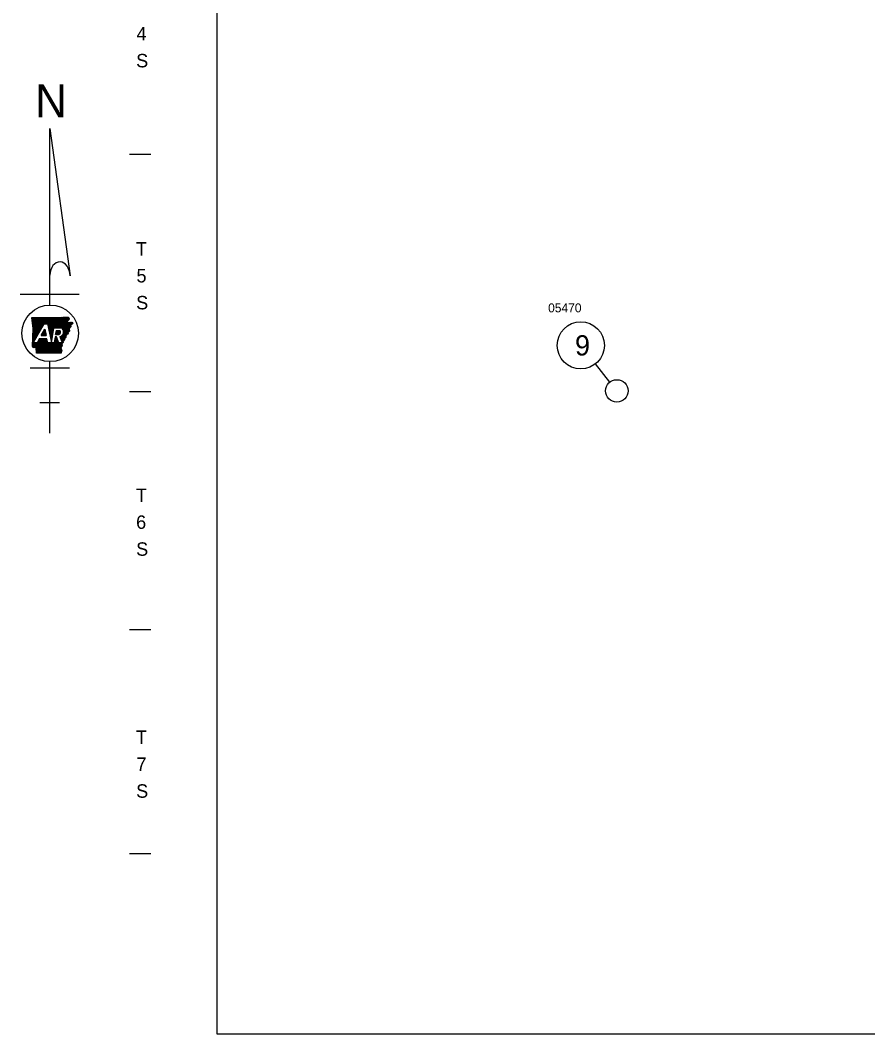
# Model space of a CAD drawing. Extents: x -33639 to 34530, y -17264 to 5867.
# Drawn here: x 4455 to 8232, y -3279 to 1239 of the extents above; entities that cross this region are included whole.
import ezdxf

# ---------------------------------------------------------------- set-up
doc = ezdxf.new("R2010")
doc.units = 0
for name, color, linetype in [('2', 7, 'Continuous'), ('Default', 7, 'Continuous'), ('R_Annotation', 7, 'Continuous'), ('R_No Plot', 7, 'Continuous')]:
    doc.layers.add(name, color=color, linetype=linetype)

msp = doc.modelspace()

# ---------------------------------------------------------------- linework, layer by layer
at = {"layer": 'Default'}
for p, q in [((5037.5, 639.8), (4942.5, 639.8)), ((5037.5, -416.9), (4942.5, -416.9)), ((5037.5, -1478.9), (4942.5, -1478.9)), ((5037.5, -2478.1), (4942.5, -2478.1))]:
    msp.add_line(p, q, dxfattribs=at)
at = {"layer": 'R_Annotation'}
for p, q in [((4586.6, 757.1), (4677.5, 100.1)), ((4586.6, -30.8), (4586.6, 757.1)), ((4455, 17.9), (4718.1, 17.9)), ((4506.7, -87.2), (4507.8, -86.2)), ((4507.1, -90.3), (4511.3, -86.2)), ((4507.5, -93.4), (4514.8, -86.2)), ((4507.9, -96.5), (4518.3, -86.2)), ((4508.3, -99.6), (4521.7, -86.2)), ((4508.7, -102.7), (4525.2, -86.2)), ((4509, -105.8), (4528.7, -86.2)), ((4509.4, -108.9), (4532.2, -86.2)), ((4509.8, -112), (4535.7, -86.2)), ((4510.2, -115.1), (4539.1, -86.2)), ((4510.6, -118.2), (4542.6, -86.2)), ((4511, -121.3), (4546.1, -86.2)), ((4511.4, -124.4), (4549.6, -86.2)), ((4511.7, -127.5), (4553.1, -86.2)), ((4511.9, -162.2), (4588, -86.1)), ((4512, -158.6), (4584.5, -86.1)), ((4512.1, -155), (4581, -86.1)), ((4512.1, -130.6), (4556.5, -86.2)), ((4512.2, -151.4), (4577.5, -86.1)), ((4512.3, -147.8), (4574, -86.2)), ((4512.5, -144.2), (4570.5, -86.2)), ((4512.5, -133.7), (4560, -86.2)), ((4512.6, -140.6), (4567, -86.2)), ((4512.7, -137), (4563.5, -86.2)), ((4563.6, -114), (4591.4, -86.1)), ((4567.1, -114), (4594.9, -86.1)), ((4570.5, -114), (4598.5, -86.1)), ((4574, -114), (4602, -86)), ((4576.2, -115.3), (4605.5, -86)), ((4576.8, -118.2), (4609.1, -85.9)), ((4577.4, -121), (4612.6, -85.9)), ((4578, -123.9), (4616.1, -85.8)), ((4578.6, -126.8), (4619.7, -85.7)), ((4579.3, -129.6), (4623.2, -85.7)), ((4579.9, -132.5), (4626.8, -85.6)), ((4580.5, -135.4), (4630.3, -85.6)), ((4581.1, -138.2), (4633.8, -85.5)), ((4581.7, -141.1), (4637.4, -85.5)), ((4582.3, -144), (4640.9, -85.4)), ((4582.9, -146.9), (4644.4, -85.4)), ((4583.6, -149.7), (4648, -85.3)), ((4584.2, -152.6), (4651.6, -85.2)), ((4608.4, -131.9), (4655.1, -85.1)), ((4611.9, -131.9), (4658.7, -85)), ((4615.3, -131.9), (4662.3, -85)), ((4618.8, -131.9), (4665.8, -84.9)), ((4622.3, -131.9), (4669.4, -84.8)), ((4625.8, -131.9), (4670.2, -87.5)), ((4629.3, -131.9), (4671.8, -89.3)), ((4511.5, -173), (4549.6, -134.9)), ((4511.6, -169.4), (4554.2, -126.9)), ((4511.7, -165.8), (4558.7, -118.8)), ((4512.9, -199.8), (4561.5, -114)), ((4561.5, -114), (4575.9, -114)), ((4605.2, -131.9), (4639, -131.9)), ((4632.7, -131.9), (4672.3, -92.3)), ((4636.2, -131.9), (4664.3, -103.8)), ((4639.4, -132.2), (4663.7, -107.9)), ((4641.3, -133.8), (4667.3, -107.8)), ((4643, -135.6), (4671, -107.6)), ((4644.4, -162), (4671, -135.4)), ((4644.5, -137.5), (4674.7, -107.4)), ((4645.8, -139.7), (4678.3, -107.2)), ((4646.9, -142.2), (4682, -107)), ((4647.4, -155.5), (4679, -123.9)), ((4647.7, -144.8), (4685.3, -107.2)), ((4648.1, -147.8), (4686.9, -109)), ((4648.2, -151.3), (4678.6, -120.8)), ((4675.1, -131.3), (4679.4, -127)), ((4685.4, -114.1), (4688.6, -110.9)), ((4510.9, -191), (4526.9, -175)), ((4511, -187.4), (4531.5, -167)), ((4511.1, -183.8), (4536, -159)), ((4511.3, -180.2), (4540.5, -150.9)), ((4511.4, -176.6), (4545.1, -142.9)), ((4548.6, -166.1), (4564.5, -138)), ((4548.6, -166.1), (4570.5, -166.1)), ((4548.8, -166.1), (4566.7, -148.2)), ((4552.3, -166.1), (4567.3, -151.1)), ((4553, -158.5), (4566.1, -145.3)), ((4555.8, -166.1), (4567.9, -153.9)), ((4557.5, -150.4), (4565.5, -142.5)), ((4559.2, -166.1), (4568.5, -156.8)), ((4562, -142.4), (4564.9, -139.6)), ((4562.7, -166.1), (4569.2, -159.7)), ((4566.2, -166.1), (4569.8, -162.6)), ((4569.7, -166.1), (4570.4, -165.4)), ((4584.8, -155.5), (4604.6, -135.7)), ((4585.4, -158.3), (4603.8, -139.9)), ((4586, -161.2), (4603.1, -144.1)), ((4586.6, -164.1), (4602.3, -148.4)), ((4587.2, -166.9), (4601.6, -152.6)), ((4587.9, -169.8), (4600.9, -156.8)), ((4588.5, -172.7), (4600.1, -161)), ((4589.1, -175.5), (4599.4, -165.2)), ((4589.7, -178.4), (4598.7, -169.4)), ((4590.3, -181.3), (4597.9, -173.7)), ((4590.9, -184.2), (4597.2, -177.9)), ((4607.3, -192.1), (4619.4, -180.1)), ((4608.1, -187.9), (4618.5, -177.5)), ((4608.8, -183.7), (4617.5, -175)), ((4609.6, -179.5), (4616.5, -172.5)), ((4610.3, -175.2), (4613, -172.5)), ((4616.6, -172.5), (4610.8, -172.5)), ((4612.5, -162.3), (4627, -162.3)), ((4612.6, -162.3), (4630.9, -144)), ((4613.3, -158.1), (4627.4, -144)), ((4614, -153.9), (4623.9, -144)), ((4614.7, -149.7), (4620.4, -144)), ((4615.5, -145.5), (4617, -144)), ((4615.7, -144), (4631.6, -144)), ((4616, -162.3), (4632.8, -145.5)), ((4626.7, -199.8), (4616.6, -172.5)), ((4619.5, -162.3), (4634, -147.8)), ((4623, -162.3), (4634.6, -150.7)), ((4626.5, -162.3), (4634.3, -154.5)), ((4630.9, -171), (4641.5, -199.8)), ((4631.2, -171.8), (4632.2, -170.7)), ((4632.1, -174.3), (4638.7, -167.7)), ((4633, -176.9), (4671.7, -138.3)), ((4634, -179.4), (4672.3, -141.1)), ((4634.9, -182), (4673, -143.9)), ((4635.9, -184.5), (4673.6, -146.7)), ((4636.8, -187), (4657.7, -166.1)), ((4637.7, -189.6), (4657.3, -170)), ((4638.7, -192.1), (4656.9, -173.9)), ((4661.7, -162.1), (4666.6, -157.2)), ((4510.1, -216.2), (4526.5, -199.8)), ((4510.2, -212.7), (4523.1, -199.8)), ((4510.3, -209.1), (4519.6, -199.8)), ((4510.4, -205.5), (4516.1, -199.8)), ((4510.5, -201.8), (4513.3, -199.1)), ((4510.7, -198.2), (4517.8, -191.1)), ((4510.8, -194.6), (4522.4, -183.1)), ((4511.4, -218.4), (4548, -181.8)), ((4529.6, -199.8), (4512.9, -199.8)), ((4513.5, -219.8), (4551.5, -181.8)), ((4516, -220.8), (4555, -181.8)), ((4520.1, -220.1), (4558.5, -181.8)), ((4523.7, -220.1), (4562, -181.8)), ((4526.4, -220.8), (4565.4, -181.8)), ((4526.5, -227.7), (4572.4, -181.8)), ((4526.5, -224.2), (4568.9, -181.8)), ((4526.5, -231.1), (4574.2, -183.4)), ((4526.5, -234.6), (4574.8, -186.3)), ((4526.5, -238.1), (4575.5, -189.2)), ((4526.5, -241.6), (4576.1, -192)), ((4526.6, -245), (4576.7, -194.9)), ((4539.8, -181.8), (4529.6, -199.8)), ((4530.1, -245), (4577.3, -197.8)), ((4533.5, -192.8), (4544.5, -181.8)), ((4533.6, -245), (4578.8, -199.8)), ((4537, -245), (4582.3, -199.8)), ((4538.1, -184.8), (4541.1, -181.8)), ((4573.9, -181.8), (4539.8, -181.8)), ((4540.5, -245), (4585.7, -199.8)), ((4544, -245), (4589.2, -199.8)), ((4547.5, -245), (4592.7, -199.8)), ((4550.9, -245), (4596.2, -199.8)), ((4554.4, -245), (4599.7, -199.8)), ((4557.9, -245), (4603.2, -199.8)), ((4561.4, -245), (4621.3, -185.1)), ((4564.9, -245.1), (4622.2, -187.7)), ((4568.3, -245.1), (4623.2, -190.2)), ((4571.8, -245.1), (4624.1, -192.8)), ((4575.3, -245.1), (4625, -195.3)), ((4606, -199.8), (4577.7, -199.8)), ((4578.8, -245.1), (4626, -197.9)), ((4582.2, -245.1), (4627.5, -199.8)), ((4585.7, -245.1), (4631, -199.8)), ((4589.2, -245.1), (4634.5, -199.8)), ((4591.5, -187), (4596.5, -182.1)), ((4592.2, -189.9), (4595.7, -186.3)), ((4592.7, -245.1), (4638, -199.8)), ((4592.8, -192.8), (4595, -190.5)), ((4593.4, -195.6), (4594.3, -194.8)), ((4596.2, -245.1), (4639.2, -202.1)), ((4599.6, -245.1), (4639.3, -205.4)), ((4603.1, -245.1), (4639.5, -208.8)), ((4606.6, -196.3), (4620.3, -182.6)), ((4606.6, -245.1), (4639.6, -212.1)), ((4610.1, -245.1), (4633.9, -221.3)), ((4613.5, -245.1), (4635, -223.7)), ((4641.5, -199.8), (4626.7, -199.8)), ((4639.6, -194.7), (4650.3, -184)), ((4640.6, -197.2), (4648.8, -189)), ((4617, -245.1), (4636, -226.1)), ((4620.5, -245.1), (4637.1, -228.5)), ((4624, -245.1), (4638.2, -230.9)), ((4627.4, -245.2), (4639.1, -233.5)), ((4630.9, -245.2), (4637.5, -238.6)), ((4634.4, -245.2), (4635.9, -243.6)), ((4498.8, -310), (4674.3, -310)), ((4586.6, -602.6), (4586.6, -282.9)), ((7082.7, -374.3), (7018.3, -292.8)), ((4542.7, -465.8), (4630.4, -465.8))]:
    msp.add_line(p, q, dxfattribs=at)
for points in [[(4506.6, -86.2), (4554.6, -86.2), (4596.8, -86.1), (4646.6, -85.3), (4669.6, -84.8)], [(4506.6, -86.2), (4554.6, -86.2), (4596.8, -86.1), (4646.5, -85.3), (4669.6, -84.8)], [(4511.9, -160.9), (4512.7, -135.5), (4506.6, -86.2)], [(4510.1, -216.2), (4512.7, -135.5), (4506.6, -86.2)], [(4575.9, -114), (4593.8, -197.5), (4605.2, -131.9)], [(4684.7, -106.9), (4688.9, -111.2), (4678.5, -119.7), (4679.6, -128.3), (4670.7, -134.2), (4673.8, -147.4), (4666.9, -153.7), (4666.3, -160.5), (4658, -163.5), (4656.7, -176.3), (4650.7, -182.7), (4647.8, -192.4), (4639.1, -200.4), (4639.7, -214.4), (4633.8, -221.1), (4639.2, -233.2), (4635.5, -245.2)], [(4662.5, -108), (4685, -106.8)], [(4662.5, -108), (4685, -106.8)], [(4510.1, -216.2), (4511.9, -160.9)], [(4564.5, -138), (4570.5, -166.1)], [(4610.8, -172.5), (4606, -199.8)], [(4612.5, -162.3), (4615.7, -144)], [(4635.5, -245.2), (4526.6, -245), (4526.5, -220.9)], [(4635.5, -245.2), (4526.6, -245), (4526.5, -220.9)], [(4577.7, -199.8), (4573.9, -181.8)]]:
    msp.add_lwpolyline(points, dxfattribs=at)
for centre, radius in [((6953.2, -210.4), 105), ((7113.7, -413.5), 50)]:
    msp.add_circle(centre, radius, dxfattribs=at)
for centre, major_axis, ratio, start_param, end_param in [((4632, 98.6), (-1.9, 63.2), 0.719778, 4.712385, 7.768526), ((4626.4, -149.7), (-21.8, 0), 0.999987, 1.777838, 4.099264), ((4623.5, -151.7), (-11.1, 0), 0.999987, 1.887169, 3.90762)]:
    msp.add_ellipse(centre, major_axis=major_axis, ratio=ratio, start_param=start_param, end_param=end_param, dxfattribs=at)
msp.add_ellipse((4588.6, -156.8), major_axis=(126, 0), ratio=0.999976, dxfattribs=at)
for points in [[(4669.6, -84.8), (4669.8, -86.1), (4670.2, -86.8), (4670.2, -88), (4670.7, -88.6), (4671.6, -89.1), (4672.3, -90), (4672.5, -91), (4672.3, -92), (4672.2, -93.2), (4672.1, -94.2), (4671.9, -95.1), (4671.2, -95.9), (4670.6, -96.4), (4669.9, -97), (4669.5, -97.7), (4668.7, -98.4), (4667.9, -99.1), (4667.3, -99.8), (4666.7, -100.6), (4666.4, -101.5), (4665.7, -102.2), (4665.2, -102.8), (4664.5, -103.6), (4664.1, -104.4), (4663.4, -105.3), (4663.3, -106.2), (4662.8, -106.9), (4662.8, -107)], [(4669.6, -84.8), (4669.8, -86.1), (4670.2, -86.8), (4670.2, -88), (4670.7, -88.6), (4671.6, -89.1), (4672.4, -90), (4672.5, -91), (4672.3, -92), (4672.3, -93.2), (4672.1, -94.2), (4672, -95.1), (4671.2, -95.8), (4670.6, -96.4), (4669.9, -97), (4669.5, -97.7), (4668.7, -98.4), (4667.9, -99.1), (4667.3, -99.8), (4666.7, -100.6), (4666.4, -101.5), (4665.7, -102.2), (4665.2, -102.8), (4664.5, -103.6), (4664.1, -104.4), (4663.4, -105.3), (4663.3, -106.2), (4662.8, -106.9), (4662.8, -107)], [(4673.4, -135.5), (4673.5, -136.3), (4673, -137.2), (4672.8, -138.2), (4672.9, -139.1), (4671.9, -139.6), (4671.1, -140.2), (4671.6, -140.9), (4672.5, -141.5), (4673.4, -142), (4673.9, -142.6), (4674.1, -143.8), (4674.2, -144.6), (4674.6, -145.6), (4674.7, -146.4), (4674.1, -147.2), (4673.5, -147.4), (4672.8, -147.2), (4672.1, -147.2), (4671.5, -147.7), (4671, -148.6), (4670.6, -149.4), (4670.2, -150.1), (4669.9, -150.9), (4669.3, -151.8), (4668.5, -151.9), (4667.5, -152.2), (4666.9, -152.8), (4667, -153.9), (4667.6, -154.7), (4668, -155.6), (4668.3, -156.4), (4668.1, -157.4), (4667.7, -158.2), (4667.2, -158.6), (4666.9, -159.6), (4666.5, -160.3), (4666.2, -160.5), (4665.5, -160.5), (4664.7, -160.3), (4664.1, -160.4), (4663.4, -160.7), (4662.8, -160.5), (4662.1, -159.8), (4661.6, -159.2), (4661, -159), (4660.4, -159.3), (4660.3, -160.3), (4660.6, -161.3), (4660.8, -162.7), (4660.6, -163.5), (4660.5, -164.9)], [(4684.7, -106.9), (4685, -106.8), (4686, -107.9), (4686.5, -108.8), (4687.1, -109.3), (4687.9, -109.6), (4688.4, -110.3), (4688.8, -111), (4688.6, -111.7), (4687.8, -111.7), (4686.9, -111.9), (4686, -111.8), (4685.3, -112.4), (4685.9, -113.2), (4686.8, -114), (4687, -114.8), (4686.5, -115.5), (4685.6, -116), (4684.7, -116.3), (4683.8, -117), (4683.4, -117.7), (4682.5, -118), (4681.6, -118.3), (4680.8, -118.4), (4679.8, -118.6), (4678.9, -119), (4678.5, -119.8), (4678.6, -120.9), (4678.6, -122), (4679.6, -122.4), (4680.4, -122.5), (4681.3, -122.9), (4681.2, -123.5), (4680.5, -124.4), (4679.8, -125), (4679.1, -125.4), (4678.4, -126), (4678.6, -126.6), (4679.2, -127), (4679.7, -127.7), (4679.6, -128.3), (4678.9, -128.8), (4678.1, -128.6), (4677.6, -127.8), (4676.9, -127.6), (4676.3, -127.3), (4675.7, -127.7), (4675.7, -128.6), (4675.5, -129.5), (4675.7, -130.2), (4675.9, -131.1), (4675.9, -131.9), (4675.7, -132.9), (4675.2, -133.9), (4674.6, -134.2), (4674.3, -133.1), (4674.2, -132.2), (4673.8, -131.6), (4673.4, -131.6), (4672.7, -132.1), (4672.1, -132.8), (4671.2, -133.5), (4670.7, -134.2), (4671, -135.2), (4671.6, -135.4), (4672.1, -135.2), (4672.4, -134.6), (4672.9, -134.5), (4673.4, -135.5)], [(4660.5, -164.9), (4659.4, -165.7), (4659, -166.5), (4656.3, -166.3), (4656.4, -167.2), (4655.5, -167.7), (4654.6, -168.3), (4655.1, -169), (4656, -169.7), (4656.9, -170.2), (4657.5, -170.7), (4657.6, -171.9), (4657.8, -172.7), (4658.1, -173.8), (4658.2, -174.5), (4657.6, -175.4), (4657, -175.6), (4656.4, -175.3), (4655.6, -175.3), (4655, -175.9), (4654.5, -176.7), (4654.1, -177.6), (4653.7, -178.3), (4653.4, -179), (4652.8, -179.9), (4652, -180.1), (4651, -180.3), (4650.4, -180.9), (4650.5, -182.1), (4651.1, -182.8), (4651.5, -183.7), (4651.8, -184.5), (4651.7, -185.5), (4651.2, -186.3), (4650.7, -186.7), (4650.4, -187.7), (4650.1, -188.4), (4649.7, -188.6), (4649, -188.6), (4648.2, -188.4), (4647.6, -188.5), (4647, -188.8), (4646.3, -188.6), (4645.7, -187.9), (4645.1, -187.3), (4644.5, -187.1), (4643.9, -187.5), (4643.8, -188.5), (4644.1, -189.5), (4644.4, -190.8), (4644.1, -191.6), (4644, -193)], [(4526.5, -220.9), (4526.6, -221), (4526.1, -220.6), (4525.3, -220.2), (4524.4, -220.2), (4523.3, -220), (4522.4, -219.9), (4521.5, -219.3), (4520.4, -220), (4519.3, -220.4), (4518.7, -219.9), (4517.8, -220.3), (4517.2, -220.1), (4516.2, -220.8), (4515.2, -220.5), (4514.5, -220.7), (4513.6, -220.7), (4513.4, -219.7), (4512.5, -219.6), (4511.8, -219.1), (4511.3, -218.1), (4510.9, -217.3), (4510.1, -216.2)], [(4526.5, -220.9), (4526.6, -221), (4526.1, -220.6), (4525.3, -220.2), (4524.4, -220.2), (4523.3, -220), (4522.4, -219.9), (4521.4, -219.3), (4520.4, -220), (4519.3, -220.4), (4518.7, -219.9), (4517.8, -220.3), (4517.2, -220.1), (4516.2, -220.8), (4515.2, -220.5), (4514.5, -220.7), (4513.6, -220.7), (4513.4, -219.7), (4512.5, -219.6), (4511.8, -219.1), (4511.3, -218.1), (4510.9, -217.3), (4510.1, -216.2)], [(4640, -204.2), (4639.7, -204.9), (4639.4, -206.1), (4639.5, -207.1), (4639.9, -208), (4640.6, -208.4), (4641.4, -209.1), (4641.4, -210.2), (4640.9, -210.5), (4639.8, -210.3), (4639, -209.9), (4638.4, -210.1), (4637.5, -210.6), (4636.8, -210.7), (4636.8, -212.1), (4637.7, -213.1), (4638.5, -213.1), (4639.5, -213.2), (4639.8, -214.3), (4639.2, -215.2), (4638.4, -215.6), (4637.2, -215.1), (4636.4, -214.5), (4635.6, -214), (4634.6, -213.7), (4634, -213.8), (4633.8, -215.1), (4634.2, -216.2), (4635, -217), (4635.7, -218), (4635.6, -218.8), (4635.1, -219), (4634.1, -219.2), (4633.6, -219.5), (4633.4, -219.7), (4633.7, -220.7), (4634, -221.8), (4634, -222.7), (4633.6, -223.4), (4633.1, -224.6), (4633.2, -225.4), (4633.6, -225.7), (4634, -225.6), (4634.6, -225.2), (4635, -224.7), (4635.3, -224.1), (4635.9, -223.6), (4636.7, -224.1), (4636.9, -225), (4636.4, -225.8), (4635.8, -226.2), (4635.1, -226.5), (4634.5, -227.1), (4634.6, -227.9), (4635.1, -228.3), (4636.2, -228.1), (4636.9, -227.7), (4637.3, -227.4), (4637.8, -226.8), (4638.1, -226.3), (4638.5, -225.8), (4639.2, -225.6), (4639.5, -226.1), (4639.4, -227.1), (4639, -228.1), (4638.4, -228.8), (4637.8, -229.4), (4637, -230.6), (4637.2, -231.8), (4637.5, -232.7), (4637.9, -233.4), (4638.6, -233.3), (4639.4, -233.2), (4639.8, -233.5), (4639.8, -234.4), (4639.2, -235.2), (4638.6, -236), (4638.4, -237), (4638.5, -237.8), (4638.5, -238.4), (4638.2, -239.2), (4637.8, -239.6), (4636.7, -239.6), (4635.6, -239.5), (4634.9, -239.8), (4635.1, -240.8), (4635.7, -241.6), (4636.2, -242), (4636.9, -242.8), (4637.2, -243.5), (4637.1, -244.1), (4636.7, -244.6), (4635.5, -245.2)], [(4640, -204.2), (4639.7, -204.9), (4639.4, -206.1), (4639.5, -207.1), (4639.9, -208), (4640.6, -208.4), (4641.4, -209.1), (4641.4, -210.2), (4640.9, -210.5), (4639.8, -210.3), (4639, -209.9), (4638.4, -210.1), (4637.5, -210.6), (4636.8, -210.7), (4636.8, -212.1), (4637.7, -213.1), (4638.5, -213.1), (4639.5, -213.2), (4639.8, -214.3), (4639.2, -215.2), (4638.4, -215.6), (4637.2, -215.1), (4636.4, -214.5), (4635.6, -214), (4634.6, -213.7), (4634, -213.8), (4633.8, -215.1), (4634.2, -216.2), (4635, -217), (4635.7, -218), (4635.6, -218.8), (4635.1, -219), (4634.1, -219.2), (4633.6, -219.5), (4633.4, -219.7), (4633.7, -220.7), (4634, -221.8), (4634, -222.7), (4633.6, -223.4), (4633.1, -224.6), (4633.2, -225.4), (4633.6, -225.7), (4634, -225.6), (4634.6, -225.2), (4635, -224.7), (4635.3, -224.1), (4635.9, -223.6), (4636.7, -224.1), (4636.9, -225), (4636.4, -225.8), (4635.8, -226.2), (4635.1, -226.5), (4634.5, -227.1), (4634.6, -227.9), (4635.1, -228.3), (4636.2, -228.1), (4636.9, -227.7), (4637.3, -227.4), (4637.8, -226.8), (4638.1, -226.3), (4638.5, -225.8), (4639.2, -225.6), (4639.5, -226.1), (4639.4, -227.1), (4639, -228.1), (4638.4, -228.8), (4637.8, -229.4), (4637, -230.6), (4637.2, -231.8), (4637.5, -232.7), (4637.9, -233.4), (4638.6, -233.3), (4639.4, -233.2), (4639.8, -233.5), (4639.8, -234.4), (4639.2, -235.2), (4638.6, -236), (4638.4, -237), (4638.5, -237.8), (4638.5, -238.4), (4638.2, -239.2), (4637.8, -239.6), (4636.7, -239.6), (4635.6, -239.5), (4634.9, -239.8), (4635.1, -240.8), (4635.7, -241.6), (4636.2, -242), (4636.9, -242.8), (4637.2, -243.5), (4637.1, -244.1), (4636.7, -244.6), (4635.5, -245.2)], [(4644, -193), (4643.9, -193.1), (4643.4, -193.7), (4643.7, -194.8), (4644.9, -195.2), (4645.4, -196.2), (4645.4, -197.1), (4645, -198.3), (4644.5, -198.9), (4643.5, -199.1), (4642.7, -199.3), (4642.5, -200.7), (4642.2, -201.3), (4641.6, -201.5), (4640.7, -201.1), (4640.1, -200.9), (4639.5, -200.6), (4638.6, -200.1), (4638, -200.2), (4638.2, -201.5), (4638.3, -201.5), (4639, -202.5), (4639.7, -203.3), (4640, -204.2)], [(4644, -193), (4643.9, -193.1), (4643.4, -193.7), (4643.7, -194.8), (4644.9, -195.2), (4645.4, -196.2), (4645.4, -197.1), (4645, -198.3), (4644.5, -198.9), (4643.5, -199.1), (4642.7, -199.3), (4642.5, -200.7), (4642.2, -201.3), (4641.6, -201.5), (4640.7, -201.1), (4640.1, -200.9), (4639.5, -200.6), (4638.6, -200.1), (4638, -200.2), (4638.2, -201.5), (4638.3, -201.5), (4639, -202.5), (4639.7, -203.3), (4640, -204.2)]]:
    msp.add_spline(points, degree=3, dxfattribs=at)
at = {"layer": 'R_No Plot'}
msp.add_lwpolyline([(12727.1, 4259.5), (5331.1, 4259.5), (5331.1, -3279.5), (12727.1, -3279.5)], close=True, dxfattribs=at)

# ---------------------------------------------------------------- texts
at = {"layer": '2'}
for s, p in [('4', (4972.9, 1149)), ('S', (4971.5, 1029)), ('T', (4970.3, 190)), ('5', (4972.9, 70)), ('S', (4971.5, -50)), ('T', (4970.3, -908.6)), ('6', (4971.3, -1028.6)), ('S', (4971.5, -1148.6)), ('T', (4970.3, -1987.4)), ('7', (4972.9, -2107.4)), ('S', (4971.5, -2227.4))]:
    msp.add_text(s, height=60, dxfattribs=at).set_placement(p)
at = {"layer": 'R_Annotation'}
for s, height, p in [('N', 146.7, (4521.2, 806.7)), ('9', 90, (6927.3, -255.4)), ('STS 10-03-17', 3.644, (4576.5, -281.8))]:
    msp.add_text(s, height=height, dxfattribs=at).set_placement(p)
at = {"layer": 'R_No Plot'}
msp.add_text('05470', height=40, dxfattribs=at).set_placement((6807.5, -63.3))

doc.saveas('drawing.dxf')
